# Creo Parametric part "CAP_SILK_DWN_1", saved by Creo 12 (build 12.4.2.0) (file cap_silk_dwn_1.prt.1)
Units: Custom; MM, KILOGRAM, SECS

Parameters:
  PTC_WM_ITERATION = "0"
  PTC_WM_VERSION = "-.0"
  PTC_WM_LIFECYCLE_STATE = "In Work"
  PTC_WM_LIFECYCLE = "MO_CADDocument"
  PTC_WM_CREATED_BY = "Maximilian Roepper (Z0017RMS: MO)"
  PTC_WM_CREATED_ON = "18-Sep-26 11:36:42 AM"
  PTC_WM_MODIFIED_BY = "Maximilian Roepper (Z0017RMS: MO)"
  PTC_WM_MODIFIED_ON = "18-Sep-26 11:36:46 AM"
  PDMLINKNUMBER = "PDM000071455010"
  PTC_WM_NAME = "cap_silk_dwn_1.prt"
  PTC_WM_NUMBER = "PDM000071455010"

Other parameters: WEIGHT, WEIGHT_FACTOR, WEIGHT_ADD, _MASS_TEMP, _DIFF_TEMP, MC_ERRORS, SUPPLIER

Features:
  1. coordinate system
  2. datum plane "PRT_YZ"
  3. datum plane "PRT_XY"
  4. datum plane "PRT_XZ"
  5. coordinate system
  6. datum axis
  7. datum axis
  8. datum axis
  9. coordinate system
  10. imported feature

Other named items: PRT, SIEMENS_MO, DRW_VIEW_ORG, PRT_X, PRT_Y, PRT_Z, CS0, ROUGH_GROB

Layers: 00_STD_CSYS-KSYS, 01_STD_PLANES-EBENEN, 02_STD_AXES-ACHSEN, 03_STD_CSYS-KSYS, 24_IMPORT_FEAT-IMPORT_KE

Surfaces: 10 plane, 4 cylinder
